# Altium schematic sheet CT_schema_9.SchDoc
size 287 x 160 mm
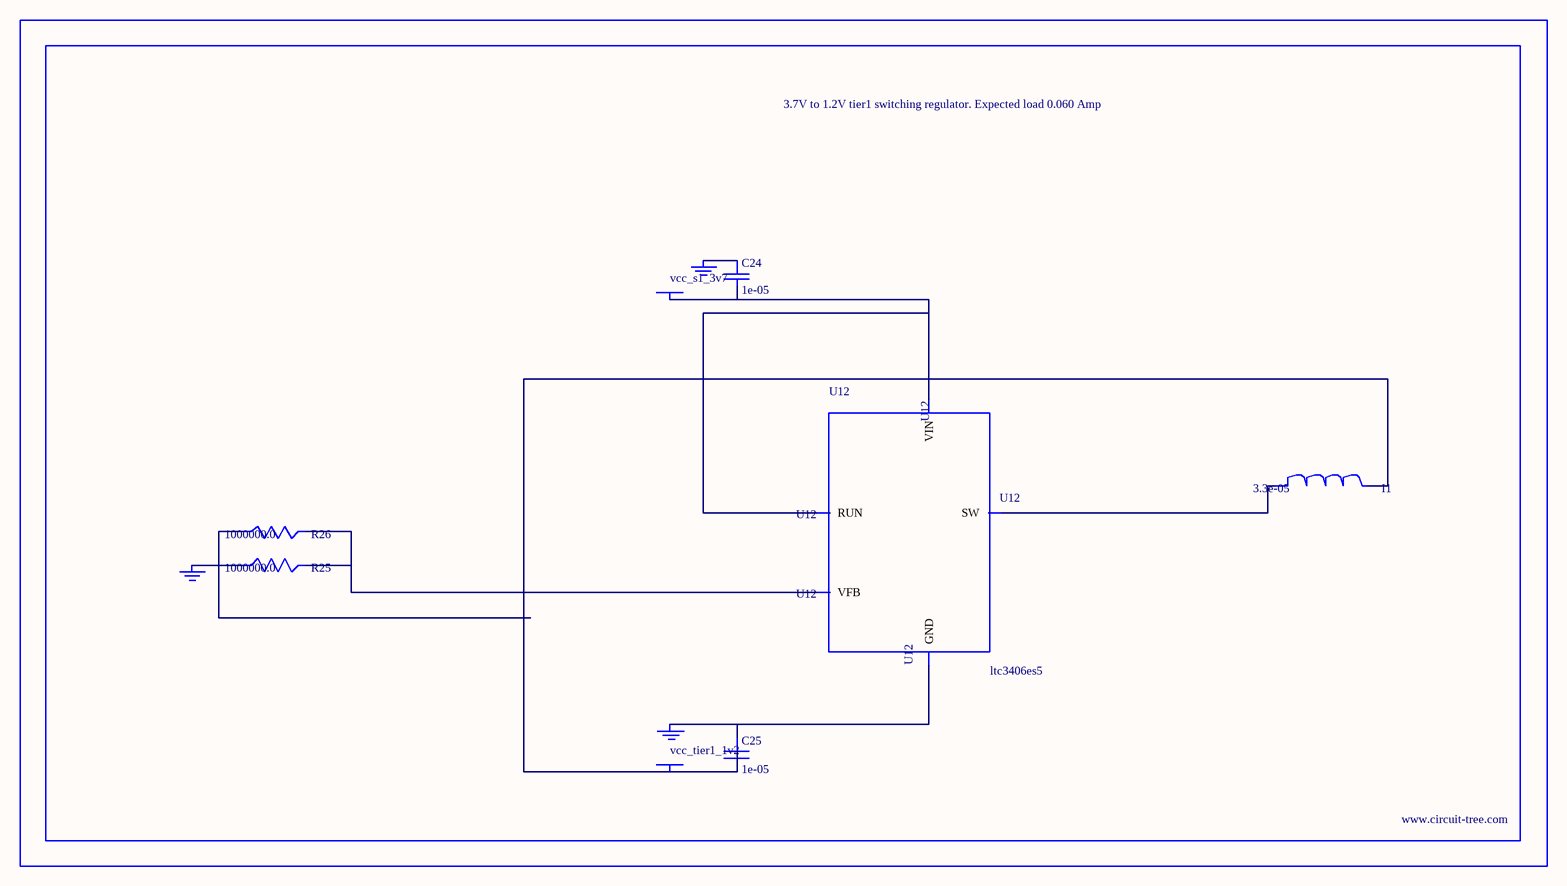
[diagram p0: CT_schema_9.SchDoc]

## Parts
BORDER8  (no value)
C24  1e-05  [C0805]
C25  1e-05  [C0805]
GND_INSTANCE_8_0  (no value)
GND_INSTANCE_8_1  (no value)
GND_INSTANCE_8_2  (no value)
I1  3.3e-05  [L1210]
POWER_INSTANCE_8_0  vcc_tier1_1v2
POWER_INSTANCE_8_1  vcc_s1_3v7
R25  1000000.0  [R0603]
R26  1000000.0  [R0603]
U12  ltc3406es5  [TSOT-23-5]

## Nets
NetC24_1: C24.1 GND_INSTANCE_8_1.0(GND)
NetC24_2: C24.2 POWER_INSTANCE_8_1.0(PWR) U12.1(RUN) U12.4(VIN)
NetC25_1: C25.1 GND_INSTANCE_8_0.0(GND) U12.2(GND)
NetC25_2: C25.2 I1.2 POWER_INSTANCE_8_0.0(PWR) R26.1
NetGND_INSTANCE_8_2_0: GND_INSTANCE_8_2.0(GND) R25.1
NetI1_1: I1.1 U12.3(SW)
NetR25_2: R25.2 R26.2 U12.5(VFB)

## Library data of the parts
BORDER8 = BORDER_PAGE8
C24 C25 = C0805C106K8RACTU
GND_INSTANCE_8_0-GND_INSTANCE_8_2 = GND
I1 = L1210R330MDWIT
POWER_INSTANCE_8_0 POWER_INSTANCE_8_1 = PWR
R25 R26 = RC0603JR-071ML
